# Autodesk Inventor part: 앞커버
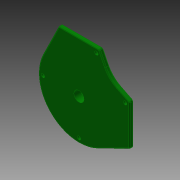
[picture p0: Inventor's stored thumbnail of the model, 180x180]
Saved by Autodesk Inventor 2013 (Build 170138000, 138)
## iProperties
Created: 2017-05
Part Number: 앞커버
Material: 알루미늄 6061
Document SubType Name: Modeling
Designer: mduedu
Density: 2.71 g/cm^3
Mass: 725.228 g
Surface Area: 595.074 cm^2
Volume: 267.612 cm^3
Author: mduedu
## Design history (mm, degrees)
sketch "스케치1"
  geometry: L1 (-71.801, 35.28)-(-40, 100); L2 (-40, 100)-(40, 100); L3 (40, 100)-(52.248, 75.073); L4 (35.28, 71.801)-(59.768, 59.768); L5 (100, 40)-(100, -40); L6 (100, -40)-(35.28, -71.801); L7 (75.073, 52.248)-(100, 40); L8 (59.768, 59.768)-(71.801, 35.28); L9 (33.075, -67.313)-(95, -36.886); L10 (95, -36.886)-(95, 36.886); L11 (95, 36.886)-(72.868, 47.76); L12 (47.76, 72.868)-(36.886, 95); L13 (36.886, 95)-(-36.886, 95); L14 (-36.886, 95)-(-67.313, 33.075); A1 r 80 centre (0, 0) between (71.801, 35.28) and (-71.801, 35.28); A2 r 80 centre (0, 0) between (35.28, -71.801) and (71.801, 35.28); A3 r 80 centre (0, 0) between (-71.801, 35.28) and (35.28, -71.801); A4 r 50 centre (97.123, 97.123) between (52.248, 75.073) and (75.073, 52.248); A5 r 55 centre (97.123, 97.123) between (47.76, 72.868) and (72.868, 47.76); A6 r 75 centre (0, 0) between (-67.313, 33.075) and (33.075, -67.313); 3 further points
  constraints: 29 end point, 15 tangent, 14 point on circle, 6 centre point, 2 midpoint, 2 perpendicular, 2 point on line, 1 coincident, 1 horizontal, 1 horizontal alignment, 1 vertical alignment, 6 other
  dimensions: "d0" = 160 diameter of A1; "d1" = 100 distance from line of L2 point (0, 0); "d2" = 100 distance from line of L5 point (0, 0); "d3" = 80 distance of L1.end L2.end; "d4" = 80 distance of L5.start L5.end; "d5" = 50 radius of A4; "d6" = 5 distance between parallel lines of L13 L2
extrude "돌출1" new body sketch "스케치1" distance "d7" = 5; taper "d8" = 0 deg
fillet "모깎기1" dims "d9" = 3
sketch "스케치2"
  geometry: C1 r 22 at (0, 0); 1 further point
  constraints: 1 centre point, 1 coincident
  dimensions: "d10" = 44 diameter of C1
extrude "돌출2" join sketch "스케치2" distance "d11" = 12.5; taper "d12" = 0 deg
sketch "스케치3"
  geometry: C1 r 18.5 at (0, 0); 1 further point
  constraints: 1 centre point, 1 coincident
  dimensions: "d13" = 37 diameter of C1
extrude "돌출3" cut sketch "스케치3" distance "d14" = 9; taper "d15" = 0 deg
sketch "스케치5"
  geometry: L1 (-67.313, 33.075)-(-37.71, 93.323) reference; L2 (-35.017, 95)-(35.017, 95) reference; L3 (37.71, 93.323)-(47.76, 72.868) reference; L4 (72.868, 47.76)-(93.323, 37.71) reference; L5 (95, 35.017)-(95, -35.017) reference; L6 (93.323, -37.71)-(33.075, -67.313) reference; L7 (93.323, 37.71)-(72.868, 47.76) reference; L8 (95, -35.017)-(95, 35.017) reference; L9 (35.017, 95)-(-35.017, 95) reference; L10 (47.76, 72.868)-(37.71, 93.323) reference; C1 r 4 at (-71, 0); C2 r 4 at (0, -71); C3 r 4 at (91, 34.394); C4 r 4 at (34.394, 91); A1 r 75 centre (0, 0) between (-67.313, 33.075) and (33.075, -67.313) reference; A2 r 3 centre (-35.017, 92) between (-35.017, 95) and (-37.71, 93.323) reference; A3 r 3 centre (35.017, 92) between (37.71, 93.323) and (35.017, 95) reference; A4 r 55 centre (97.123, 97.123) between (47.76, 72.868) and (72.868, 47.76) reference; A5 r 3 centre (92, 35.017) between (95, 35.017) and (93.323, 37.71) reference; A6 r 3 centre (92, -35.017) between (93.323, -37.71) and (95, -35.017) reference; A7 r 75 centre (0, 0) between (-67.313, 33.075) and (33.075, -67.313) reference; 5 further points
  constraints: 6 tangent, 4 centre point, 4 coincident, 3 equal radius, 1 horizontal alignment, 1 vertical alignment
  dimensions: "d39" = 8 diameter of C1
  node "절단 모서리 투영1"
sketch "스케치7"
  geometry: L1 (100, -38.131)-(100, 38.131) reference; L2 (98.323, 40.824)-(75.073, 52.248) reference; L3 (52.248, 75.073)-(40.824, 98.323) reference; L4 (38.131, 100)-(-38.131, 100) reference; L5 (-40.824, 98.323)-(-71.801, 35.28) reference; L6 (35.28, -71.801)-(98.323, -40.824) reference; L7 (35.017, 96)-(-35.017, 96) reference; L8 (48.658, 73.309)-(38.607, 93.764) reference; L9 (93.764, 38.607)-(73.309, 48.658) reference; L10 (96, -35.017)-(96, 35.017) reference; L11 (33.516, -68.211)-(93.764, -38.607) reference; L12 (-38.607, 93.764)-(-68.211, 33.516) reference; A1 r 3 centre (97, -38.131) between (98.323, -40.824) and (100, -38.131) reference; A2 r 3 centre (97, 38.131) between (100, 38.131) and (98.323, 40.824) reference; A3 r 50 centre (97.123, 97.123) between (52.248, 75.073) and (75.073, 52.248) reference; A4 r 3 centre (38.131, 97) between (40.824, 98.323) and (38.131, 100) reference; A5 r 3 centre (-38.131, 97) between (-38.131, 100) and (-40.824, 98.323) reference; A6 r 80 centre (0, 0) between (-71.801, 35.28) and (35.28, -71.801) reference; A7 r 4 centre (35.017, 92) between (38.607, 93.764) and (35.017, 96) reference; A8 r 54 centre (97.123, 97.123) between (48.658, 73.309) and (73.309, 48.658) reference; A9 r 4 centre (92, 35.017) between (96, 35.017) and (93.764, 38.607) reference; A10 r 4 centre (92, -35.017) between (93.764, -38.607) and (96, -35.017) reference; A11 r 76 centre (0, 0) between (-68.211, 33.516) and (33.516, -68.211) reference; A12 r 4 centre (-35.017, 92) between (-35.017, 96) and (-38.607, 93.764) reference; 1 further point
extrude "돌출4" join sketch "스케치7" distance "d47" = 6; taper "d48" = 0 deg
sketch "스케치6"
  geometry: 4 further points
  constraints: 4 other
hole "구멍2" sketch "스케치6" at (0, -71), (91, 34.394), (34.394, 91), (-71, 0) diameter "d40" = 3.4; stored, may be unused: countersink angle "d44" = 90 deg, drill point angle "d46" = 0 deg; dims "d41" = 6, "d42" = 7, "d43" = 4, "d45" = 8
hole "구멍1" diameter "d18" = 20; stored, may be unused: countersink angle "d22" = 90 deg, drill point angle "d24" = 118 deg; dims "d19" = 6, "d20" = 4, "d21" = 2, "d23" = 8, "d50" = 10, "d51" = 10
fillet "모깎기2" dims "d25" = 3
chamfer "모따기1" distance "d27" = 1; stored, may be unused: second distance "d28" = 2, angle "d29" = 45 deg
chamfer "모따기2" distance "d33" = 1; stored, may be unused: second distance "d34" = 2, angle "d35" = 45 deg
chamfer "모따기3" distance "d36" = 1; stored, may be unused: second distance "d37" = 2, angle "d38" = 45 deg
fillet "모깎기3" dims "d49" = 2
node "솔리드1"
node "참조1"
